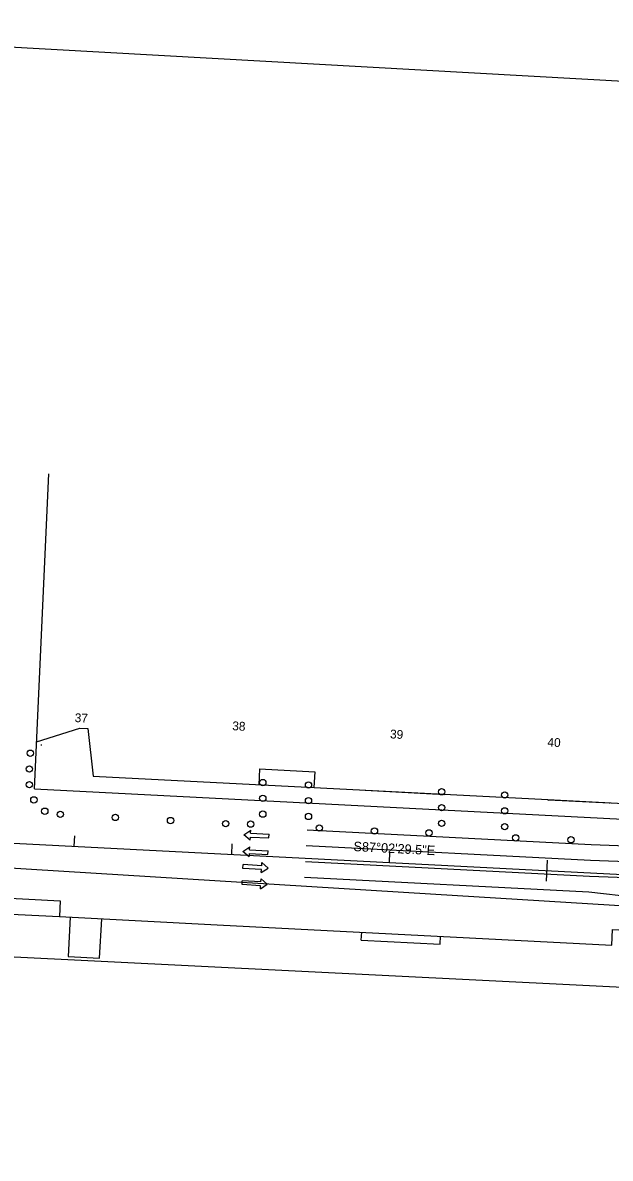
# Model space of a CAD drawing. Extents: x 679444 to 687671, y 733868 to 736107.
# Drawn here: x 682944 to 683317, y 734838 to 735558 of the extents above; entities that cross this region are included whole.
import ezdxf

# ---------------------------------------------------------------- set-up
doc = ezdxf.new("R2010")
doc.units = 0
for name, color, linetype in [('$', 7, 'Continuous'), ('border All Plan 20-40_Border 3 - Level 1', 7, 'Continuous'), ('Clipping Boundary', 7, 'Continuous'), ('MOT Stage 1', 7, 'Continuous'), ('MOT Stage 1 Lanes', 7, 'Continuous'), ('R_Horz Alg Station', 7, 'Continuous'), ('R_TYPE_A_CURB', 7, 'Continuous'), ('RW-EX', 7, 'Continuous'), ('RW-PR', 7, 'Continuous')]:
    doc.layers.add(name, color=color, linetype=linetype)

# ---------------------------------------------------------------- blocks, each defined once
blk = doc.blocks.new('BAREL_1596')
at = {"layer": 'MOT Stage 1'}
blk.add_circle((0, 0), 2.88, dxfattribs=at)
blk = doc.blocks.new('BAREL_1597')
at = {"layer": 'MOT Stage 1'}
blk.add_circle((0, 0), 2.88, dxfattribs=at)
blk = doc.blocks.new('BAREL_1598')
at = {"layer": 'MOT Stage 1'}
blk.add_circle((0, 0), 2.88, dxfattribs=at)
blk = doc.blocks.new('BAREL_1599')
at = {"layer": 'MOT Stage 1'}
blk.add_circle((0, 0), 2.88, dxfattribs=at)
blk = doc.blocks.new('BAREL_1600')
at = {"layer": 'MOT Stage 1'}
blk.add_circle((0, 0), 2.88, dxfattribs=at)
blk = doc.blocks.new('BAREL_1601')
at = {"layer": 'MOT Stage 1'}
blk.add_circle((0, 0), 2.88, dxfattribs=at)
blk = doc.blocks.new('BAREL_1602')
at = {"layer": 'MOT Stage 1'}
blk.add_circle((0, 0), 2.88, dxfattribs=at)
blk = doc.blocks.new('BAREL_1603')
at = {"layer": 'MOT Stage 1'}
blk.add_circle((0, 0), 2.88, dxfattribs=at)
blk = doc.blocks.new('BAREL_1604')
at = {"layer": 'MOT Stage 1'}
blk.add_circle((0, 0), 2.88, dxfattribs=at)
blk = doc.blocks.new('BAREL_1605')
at = {"layer": 'MOT Stage 1'}
blk.add_circle((0, 0), 2.88, dxfattribs=at)
blk = doc.blocks.new('BAREL_1606')
at = {"layer": 'MOT Stage 1'}
blk.add_circle((0, 0), 2.88, dxfattribs=at)
blk = doc.blocks.new('BAREL_1607')
at = {"layer": 'MOT Stage 1'}
blk.add_circle((0, 0), 2.88, dxfattribs=at)
blk = doc.blocks.new('BAREL_1608')
at = {"layer": 'MOT Stage 1'}
blk.add_circle((0, 0), 2.88, dxfattribs=at)
blk = doc.blocks.new('BAREL_1609')
at = {"layer": 'MOT Stage 1'}
blk.add_circle((0, 0), 2.88, dxfattribs=at)
blk = doc.blocks.new('BAREL_1636')
at = {"layer": 'MOT Stage 1'}
blk.add_circle((0, 0), 2.88, dxfattribs=at)
blk = doc.blocks.new('BAREL_1637')
at = {"layer": 'MOT Stage 1'}
blk.add_circle((0, 0), 2.88, dxfattribs=at)
blk = doc.blocks.new('BAREL_1638')
at = {"layer": 'MOT Stage 1'}
blk.add_circle((0, 0), 2.88, dxfattribs=at)
blk = doc.blocks.new('BAREL_1639')
at = {"layer": 'MOT Stage 1'}
blk.add_circle((0, 0), 2.88, dxfattribs=at)
blk = doc.blocks.new('BAREL_1640')
at = {"layer": 'MOT Stage 1'}
blk.add_circle((0, 0), 2.88, dxfattribs=at)
blk = doc.blocks.new('SARROW_191')
at = {"layer": 'MOT Stage 1'}
for p, q in [((-6, -29.4), (-6, 0)), ((0, 0), (-6, 0)), ((0, -29.4), (0, 0)), ((-6, -29.4), (-11, -29.4)), ((-3, -39.8), (-11, -29.4)), ((5, -29.4), (-3, -39.8)), ((5, -29.4), (0, -29.4))]:
    blk.add_line(p, q, dxfattribs=at)
blk = doc.blocks.new('SARROW_192')
at = {"layer": 'MOT Stage 1'}
for p, q in [((-6, -29.4), (-6, 0)), ((0, 0), (-6, 0)), ((0, -29.4), (0, 0)), ((-6, -29.4), (-11, -29.4)), ((-3, -39.8), (-11, -29.4)), ((5, -29.4), (-3, -39.8)), ((5, -29.4), (0, -29.4))]:
    blk.add_line(p, q, dxfattribs=at)
blk = doc.blocks.new('SARROW_193')
at = {"layer": 'MOT Stage 1'}
for p, q in [((-6, -29.4), (-6, 0)), ((0, 0), (-6, 0)), ((0, -29.4), (0, 0)), ((-6, -29.4), (-11, -29.4)), ((-3, -39.8), (-11, -29.4)), ((5, -29.4), (-3, -39.8)), ((5, -29.4), (0, -29.4))]:
    blk.add_line(p, q, dxfattribs=at)
blk = doc.blocks.new('SARROW_194')
at = {"layer": 'MOT Stage 1'}
for p, q in [((0, 0), (-6, 0)), ((0, -29.4), (0, 0)), ((-6, -29.4), (-6, 0)), ((-6, -29.4), (-11, -29.4)), ((-3, -39.8), (-11, -29.4)), ((5, -29.4), (-3, -39.8)), ((5, -29.4), (0, -29.4))]:
    blk.add_line(p, q, dxfattribs=at)
blk = doc.blocks.new('BAREL_1665')
at = {"layer": 'MOT Stage 1'}
blk.add_circle((0, 0), 2.88, dxfattribs=at)
blk = doc.blocks.new('BAREL_1666')
at = {"layer": 'MOT Stage 1'}
blk.add_circle((0, 0), 2.88, dxfattribs=at)
blk = doc.blocks.new('BAREL_1667')
at = {"layer": 'MOT Stage 1'}
blk.add_circle((0, 0), 2.88, dxfattribs=at)
blk = doc.blocks.new('BAREL_1668')
at = {"layer": 'MOT Stage 1'}
blk.add_circle((0, 0), 2.88, dxfattribs=at)
blk = doc.blocks.new('BAREL_1669')
at = {"layer": 'MOT Stage 1'}
blk.add_circle((0, 0), 2.88, dxfattribs=at)
blk = doc.blocks.new('BAREL_1670')
at = {"layer": 'MOT Stage 1'}
blk.add_circle((0, 0), 2.88, dxfattribs=at)
blk = doc.blocks.new('BAREL_1671')
at = {"layer": 'MOT Stage 1'}
blk.add_circle((0, 0), 2.88, dxfattribs=at)
blk = doc.blocks.new('BAREL_1672')
at = {"layer": 'MOT Stage 1'}
blk.add_circle((0, 0), 2.88, dxfattribs=at)

msp = doc.modelspace()

# ---------------------------------------------------------------- linework, layer by layer
at = {"layer": 'border All Plan 20-40_Border 3 - Level 1'}
msp.add_line((682658.17, 735557.86), (684236.65, 735470.4), dxfattribs=at)
at = {"layer": 'Clipping Boundary'}
msp.add_lwpolyline([(682208.27, 735067.14), (683202.96, 735005.68), (683576.79, 734982.58), (683585.61, 734947.81), (683582.55, 734837.97), (683533.65, 734842.79), (683477.58, 734938.67), (682209.6, 735001.84)], close=True, dxfattribs=at)
at = {"layer": 'MOT Stage 1 Lanes'}
for p, q in [((683124.65, 735046.17), (683304.73, 735036.86)), ((683124.13, 735036.18), (683304.21, 735026.87)), ((683304.73, 735036.86), (683439.64, 735031.89)), ((683123.62, 735026.19), (683303.69, 735016.89)), ((683304.21, 735026.87), (683439.13, 735021.9)), ((683123.1, 735016.21), (683303.18, 735006.9)), ((683303.69, 735016.89), (683438.61, 735011.92)), ((683303.18, 735006.9), (683370.78, 734999.38))]:
    msp.add_line(p, q, dxfattribs=at)
at = {"layer": 'R_Horz Alg Station'}
msp.add_line((682930.35, 735038.18), (683438.62, 735011.92), dxfattribs=at)
for points in [[(682977.23, 735042.44), (682976.88, 735035.78)], [(683077.09, 735037.28), (683076.75, 735030.62)], [(683176.96, 735032.11), (683176.62, 735025.46)], [(683276.83, 735026.95), (683276.14, 735013.64)]]:
    msp.add_lwpolyline(points, dxfattribs=at)
at = {"layer": 'R_TYPE_A_CURB'}
for p, q in [((682956.36, 735099.63), (682956.39, 735100.2)), ((683161.46, 735071.3), (683211.89, 735068.69)), ((683277.57, 735064.8), (683277.59, 735065.3)), ((683277.59, 735065.3), (683316.35, 735063.29)), ((683316.35, 735063.29), (683316.33, 735062.8))]:
    msp.add_line(p, q, dxfattribs=at)
at = {"layer": 'RW-EX'}
for p, q in [((682951.92, 735072.12), (682961.1, 735271.9)), ((682951.92, 735072.12), (683440.41, 735046.87)), ((682628.3, 735018.75), (682968.24, 735001.18))]:
    msp.add_line(p, q, dxfattribs=at)
msp.add_lwpolyline([(682968.24, 735001.18), (682967.74, 734991.19), (683067.68, 734986.03), (683317.82, 734973.1), (683318.3, 734983.09), (683436.82, 734976.96)], dxfattribs=at)
at = {"layer": 'RW-PR'}
for p, q in [((683094.57, 735084.77), (683094.05, 735074.78)), ((683094.57, 735084.77), (683129.52, 735082.96)), ((683129.52, 735082.96), (683129.01, 735072.98)), ((682627.74, 735008.76), (682967.74, 734991.19)), ((683159.06, 734976.3), (683159.31, 734981.29)), ((683208.99, 734973.72), (683209.25, 734978.71)), ((683159.06, 734976.3), (683208.99, 734973.72))]:
    msp.add_line(p, q, dxfattribs=at)
for points in [[(682953.3, 735102.08), (682980.75, 735110.68), (682985.75, 735110.42), (682989.19, 735080.2), (683277.18, 735065.32), (683449.96, 735056.39), (683478.52, 735054.93), (683538.96, 735061.84)], [(682974.56, 734990.84), (682973.27, 734965.87), (682993.24, 734964.84), (682994.53, 734989.81)]]:
    msp.add_lwpolyline(points, dxfattribs=at)

# ---------------------------------------------------------------- block references
at = {"layer": 'MOT Stage 1'}
for name, p, xscale, yscale, rotation in [('BAREL_1636', (682949.3, 735094.76), 0.6945420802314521, 0.6945420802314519, 87.04179557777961), ('BAREL_1637', (682948.71, 735084.78), 0.6945420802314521, 0.6945420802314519, 87.04179557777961), ('BAREL_1638', (682948.71, 735074.78), 0.6945420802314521, 0.6945420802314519, 87.04179557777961), ('BAREL_1596', (683096.63, 735076.15), 0.6945420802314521, 0.6945420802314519, 87.04179557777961), ('BAREL_1599', (683125.59, 735074.66), 0.6945420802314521, 0.6945420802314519, 87.04179557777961), ('BAREL_1603', (683209.98, 735070.29), 0.6945420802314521, 0.6945420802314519, 87.04179557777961), ('BAREL_1639', (682951.54, 735065.19), 0.6945420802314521, 0.6945420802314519, 87.04179557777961), ('BAREL_1597', (683096.63, 735066.15), 0.6945420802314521, 0.6945420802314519, 87.04179557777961), ('BAREL_1600', (683125.59, 735064.66), 0.6945420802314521, 0.6945420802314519, 87.04179557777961), ('BAREL_1604', (683249.93, 735068.23), 0.6945420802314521, 0.6945420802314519, 87.04179557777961), ('BAREL_1640', (682958.48, 735057.99), 0.6945420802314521, 0.6945420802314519, 87.04179557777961), ('BAREL_1665', (682968.27, 735055.96), 0.6945420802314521, 0.6945420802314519, 87.04179557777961), ('BAREL_1598', (683096.63, 735056.15), 0.6945420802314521, 0.6945420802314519, 87.04179557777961), ('BAREL_1605', (683209.98, 735060.29), 0.6945420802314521, 0.6945420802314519, 87.04179557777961), ('BAREL_1607', (683249.93, 735058.23), 0.6945420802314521, 0.6945420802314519, 87.04179557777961), ('BAREL_1666', (683003.22, 735054.02), 0.6945420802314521, 0.6945420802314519, 87.04179557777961), ('BAREL_1667', (683038.17, 735052.09), 0.6945420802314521, 0.6945420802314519, 87.04179557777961), ('BAREL_1668', (683073.11, 735050.15), 0.6945420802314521, 0.6945420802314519, 87.04179557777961), ('BAREL_1669', (683088.91, 735049.8), 0.6945420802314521, 0.6945420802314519, 87.04179557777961), ('BAREL_1601', (683125.59, 735054.66), 0.6945420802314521, 0.6945420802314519, 87.04179557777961), ('BAREL_1602', (683132.45, 735047.38), 0.6945420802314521, 0.6945420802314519, 115.570266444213), ('BAREL_1606', (683209.98, 735050.29), 0.6945420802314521, 0.6945420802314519, 87.04179557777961), ('BAREL_1608', (683249.93, 735048.23), 0.6945420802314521, 0.6945420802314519, 87.04179557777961), ('SARROW_191', (683100.48, 735041.03), 0.39999999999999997, 0.4, -92.95654264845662), ('BAREL_1670', (683167.39, 735045.44), 0.6945420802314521, 0.6945420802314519, 115.570266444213), ('BAREL_1671', (683202.01, 735044.26), 0.6945420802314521, 0.6945420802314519, 87.04179557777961), ('BAREL_1609', (683256.92, 735041.09), 0.6945420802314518, 0.6945420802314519, 116.71114235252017), ('SARROW_192', (683099.89, 735030.51), 0.39999999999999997, 0.4, -92.95654264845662), ('BAREL_1672', (683291.9, 735039.87), 0.6945420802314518, 0.6945420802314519, 116.71114235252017), ('SARROW_193', (683084.06, 735021.73), 0.40000000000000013, -0.40000000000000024, -93.38580215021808), ('SARROW_194', (683083.49, 735011.48), 0.40000000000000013, -0.40000000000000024, -93.38580215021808)]:
    msp.add_blockref(name, p, dxfattribs=dict(at, xscale=xscale, yscale=yscale, rotation=rotation))

# ---------------------------------------------------------------- texts
at = {"layer": '$'}
for s, p in [('37', (682977.32, 735114.53)), ('38', (683077.19, 735109.37)), ('39', (683177.16, 735104.2)), ('40', (683276.92, 735099.04))]:
    msp.add_text(s, height=5.6, rotation=357.04154, dxfattribs=at).set_placement(p)
at = {"layer": 'R_Horz Alg Station'}
msp.add_text('S87%%d02\'29.5"E', height=6, rotation=357.04154, dxfattribs=at).set_placement((683153.98, 735032.76))

doc.saveas('drawing.dxf')
